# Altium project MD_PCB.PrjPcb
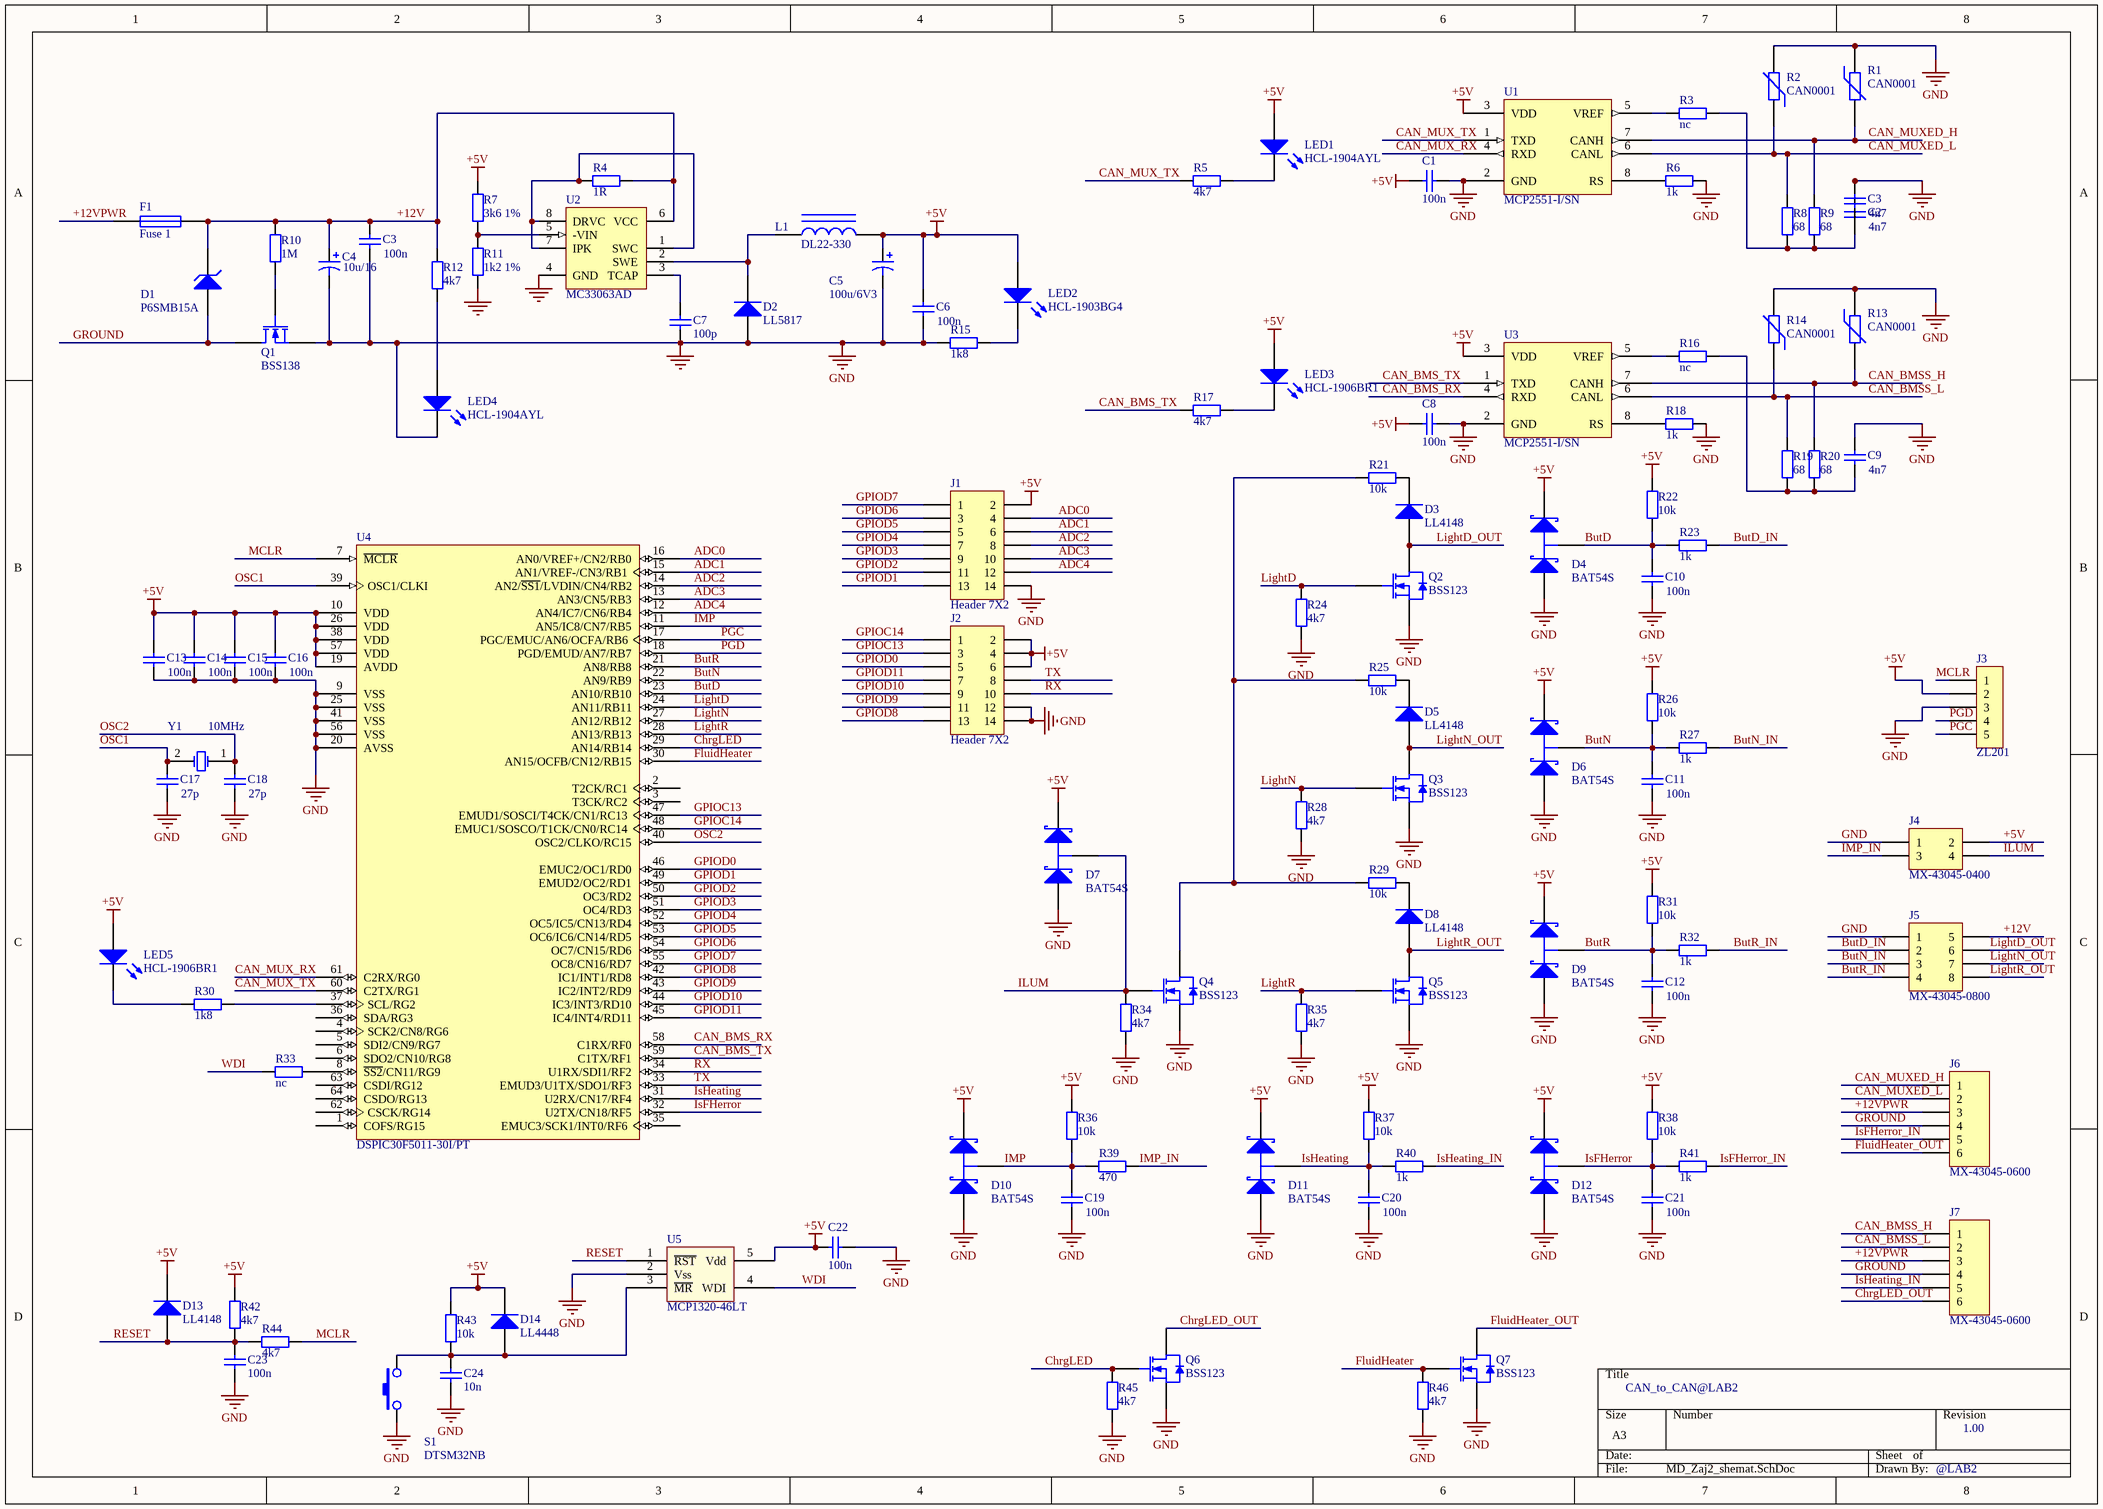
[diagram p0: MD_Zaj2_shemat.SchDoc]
1 sheet, 113 parts. Net scope: global (net labels, ports and power ports of the same name join across sheets).
Board file: PCB1.PcbDoc

## Sheet MD_Zaj2_shemat.SchDoc: CAN-to-CAN
size A3; Revision: PW-Test-Lab2; PageSetup: Record=PageOptions¦CenterHorizontal=True¦CenterVertical=True¦PrintScale=0.71¦XCorrection=1.00¦YCorrection=1.00¦PrintKind=1¦BorderSize=5000000¦LeftOffset=0¦BottomOffset=0¦Orientation=2¦PaperLength=2970¦PaperWidth=2100¦Scale=100¦PaperSource=7¦PrintQuality=1200¦MediaType=1¦DitherType=10¦PaperKind=A4¦PrintScaleMode=1

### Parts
(Parts that share a designator on the sheet are numbered #1, #2 ... from top to bottom, then left to right.)
C1  100n  [0603]
C2  4n7  [0603]
C3#1  4n7  [0603]
C3#2  100n  [0603]
C4  10u/16  [0603]
C5  100u/6V3  [0603]
C6  100n  [0603]
C7  100p  [0603]
C8  100n  [0603]
C9  4n7  [0603]
C10  100n  [0603]
C11  100n  [0603]
C12  100n  [0603]
C13  100n  [0603]
C14  100n  [0603]
C15  100n  [0603]
C16  100n  [0603]
C17  27p  [0603]
C18  27p  [0603]
C19  100n  [0603]
C20  100n  [0603]
C21  100n  [0603]
C22  100n  [0603]
C23  100n  [0603]
C24  10n  [0603]
D1  P6SMB15A  [SMB]
D2  LL5817  [0603]
D3  LL4148  [0603]
D4  BAT54S  [SOT-23_L]
D5  LL4148  [0603]
D6  BAT54S  [SOT-23_L]
D7  BAT54S  [SOT-23_L]
D8  LL4148  [0603]
D9  BAT54S  [SOT-23_L]
D10  BAT54S  [SOT-23_L]
D11  BAT54S  [SOT-23_L]
D12  BAT54S  [SOT-23_L]
D13  LL4148  [0603]
D14  LL4448  [0603]
F1  Fuse 1  [1812]
J1  Header 7X2  [HDR2X7]
J2  Header 7X2  [HDR2X7]
J3  ZL201  [HDR1X5]
J4  MX-43045-0400  [SOT-343_L]
J5  MX-43045-0800  [SO8_L]
J6  MX-43045-0600  [MHDR1X6]
J7  MX-43045-0600  [MHDR1x6]
L1  DL22-330  [AXIAL-0.9]
LED1  HCL-1904AYL  [0603]
LED2  HCL-1903BG4  [0603]
LED3  HCL-1906BR1  [0603]
LED4  HCL-1904AYL  [0603]
LED5  HCL-1906BR1  [0603]
Q1  BSS138  [SOT23_L]
Q2  BSS123  [SOT-23_L]
Q3  BSS123  [SOT-23_L]
Q4  BSS123  [SOT-23_L]
Q5  BSS123  [SOT-23_L]
Q6  BSS123  [SOT-23_L]
Q7  BSS123  [SOT-23_L]
R1  CAN0001  [0603]
R2  CAN0001  [0603]
R3  nc  [0603]
R4  1R  [0603]
R5  4k7  [0603]
R6  1k  [0603]
R7  3k6 1%  [0603]
R8  68  [0603]
R9  68  [0603]
R10  1M  [0603]
R11  1k2 1%  [0603]
R12  4k7  [0603]
R13  CAN0001  [0603]
R14  CAN0001  [0603]
R15  1k8  [0603]
R16  nc  [0603]
R17  4k7  [0603]
R18  1k  [0603]
R19  68  [0603]
R20  68  [0603]
R21  10k  [0603]
R22  10k  [0603]
R23  1k  [0603]
R24  4k7  [0603]
R25  10k  [0603]
R26  10k  [0603]
R27  1k  [0603]
R28  4k7  [0603]
R29  10k  [0603]
R30  1k8  [0603]
R31  10k  [0603]
R32  1k  [0603]
R33  nc  [0603]
R34  4k7  [0603]
R35  4k7  [0603]
R36  10k  [0603]
R37  10k  [0603]
R38  10k  [0603]
R39  470  [0603]
R40  1k  [0603]
R41  1k  [0603]
R42  4k7  [0603]
R43  10k  [0603]
R44  4k7  [0603]
R45  4k7  [0603]
R46  4k7  [0603]
S1  DTSM32NB  [0603]
U1  MCP2551-I/SN  [so8_L]
U2  MC33063AD  [SO8_N]
U3  MCP2551-I/SN  [SO8_L]
U4  DSPIC30F5011-30I/PT  [TQFP-PT64_L]
U5  MCP1320-46LT  [SOT-143_L]
Y1  10MHz  [0603]

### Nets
+5V: C1.1 C5.1 C6.1 C8.1 C13.1 C14.1 C15.1 C16.1 C22.1 D4.2(K) D6.2(K) D7.2(K) D9.2(K) D10.2(K) D11.2(K) D12.2(K) D13.2(K) D14.2(K) J1.2 J2.2 J2.4 J2.6 J3.2 J4.2 L1.2 LED1.1(A) LED2.1(A) LED3.1(A) LED5.1(A) R7.1 R22.1 R26.1 R31.1 R36.1 R37.1 R38.1 R42.1 R43.2 U1.3(VDD) U3.3(VDD) U4.10(VDD) U4.19(AVDD) U4.26(VDD) U4.38(VDD) U4.57(VDD) U5.5(Vdd)
GND: C1.2 C2.1 C3#1.1 C3#2.2 C4.2 C5.2 C6.2 C7.1 C8.2 C9.1 C10.2 C11.2 C12.2 C13.2 C14.2 C15.2 C16.2 C17.2 C18.2 C19.2 C20.2 C21.2 C22.2 C23.1 C24.1 D2.1(A) D4.1(A) D6.1(A) D7.1(A) D9.1(A) D10.1(A) D11.1(A) D12.1(A) J1.14 J2.12 J2.14 J3.3 J4.1 J5.1 LED4.2(K) Q1.2(S) Q2.2(S) Q3.2(S) Q4.2(S) Q5.2(S) Q6.2(S) Q7.2(S) R1.1 R2.2 R6.2 R11.1 R13.1 R14.2 R15.2 R18.2 R24.2 R28.2 R34.2 R35.2 R45.2 R46.2 S1.1 U1.2(GND) U2.4(GND) U3.2(GND) U4.9(VSS) U4.20(AVSS) U4.25(VSS) U4.41(VSS) U4.56(VSS) U5.2(Vss)
+12V: C3#2.1 C4.1 D1.2(K) F1.2 J5.5 R4.2 R10.1 R12.1 U2.6(VCC)
+12VPWR: F1.1 J6.3 J7.3
ADC0: J1.4 U4.16(AN0/VREF+/CN2/RB0)
ADC1: J1.6 U4.15(AN1/VREF-/CN3/RB1)
ADC2: J1.8 U4.14(AN2/~{SS1}/LVDIN/CN4/RB2)
ADC3: J1.10 U4.13(AN3/CN5/RB3)
ADC4: J1.12 U4.12(AN4/IC7/CN6/RB4)
ButD: C10.1 D4.3(C) R22.2 R23.2 U4.23(AN10/RB10)
ButD_IN: J5.2 R23.1
ButN: C11.1 D6.3(C) R26.2 R27.2 U4.22(AN9/RB9)
ButN_IN: J5.3 R27.1
ButR: C12.1 D9.3(C) R31.2 R32.2 U4.21(AN8/RB8)
ButR_IN: J5.4 R32.1
CAN_BMS_RX: U3.4(RXD) U4.58(C1RX/RF0)
CAN_BMS_TX: R17.2 U3.1(TXD) U4.59(C1TX/RF1)
CAN_BMSS_H: J7.1 R13.2 R20.1 U3.7(CANH)
CAN_BMSS_L: J7.2 R14.1 R19.1 U3.6(CANL)
CAN_MUX_RX: U1.4(RXD) U4.61(C2RX/RG0)
CAN_MUX_TX: R5.2 U1.1(TXD) U4.60(C2TX/RG1)
CAN_MUXED_H: J6.1 R1.2 R9.1 U1.7(CANH)
CAN_MUXED_L: J6.2 R2.1 R8.1 U1.6(CANL)
ChrgLED: Q6.3(G) R45.1 U4.29(AN14/RB14)
ChrgLED_OUT: J7.6 Q6.1(D)
FluidHeater: Q7.3(G) R46.1 U4.30(AN15/OCFB/CN12/RB15)
FluidHeater_OUT: J6.6 Q7.1(D)
GPIOC13: J2.3 U4.47(EMUD1/SOSCI/T4CK/CN1/RC13)
GPIOC14: J2.1 U4.48(EMUC1/SOSCO/T1CK/CN0/RC14)
GPIOD0: J2.5 U4.46(EMUC2/OC1/RD0)
GPIOD1: J1.13 U4.49(EMUD2/OC2/RD1)
GPIOD2: J1.11 U4.50(OC3/RD2)
GPIOD3: J1.9 U4.51(OC4/RD3)
GPIOD4: J1.7 U4.52(OC5/IC5/CN13/RD4)
GPIOD5: J1.5 U4.53(OC6/IC6/CN14/RD5)
GPIOD6: J1.3 U4.54(OC7/CN15/RD6)
GPIOD7: J1.1 U4.55(OC8/CN16/RD7)
GPIOD8: J2.13 U4.42(IC1/INT1/RD8)
GPIOD9: J2.11 U4.43(IC2/INT2/RD9)
GPIOD10: J2.9 U4.44(IC3/INT3/RD10)
GPIOD11: J2.7 U4.45(IC4/INT4/RD11)
GROUND: D1.1(A) J6.4 J7.4 Q1.1(D)
ILUM: D7.3(C) J4.4 Q4.3(G) R34.1
IMP: C19.1 D10.3(C) R36.2 R39.2 U4.11(AN5/IC8/CN7/RB5)
IMP_IN: J4.3 R39.1
IsFHerror: C21.1 D12.3(C) R38.2 R41.2 U4.32(U2TX/CN18/RF5)
IsFHerror_IN: J6.5 R41.1
IsHeating: C20.1 D11.3(C) R37.2 R40.2 U4.31(U2RX/CN17/RF4)
IsHeating_IN: J7.5 R40.1
LightD: Q2.3(G) R24.1 U4.24(AN11/RB11)
LightD_OUT: D3.1(A) J5.6 Q2.1(D)
LightN: Q3.3(G) R28.1 U4.27(AN12/RB12)
LightN_OUT: D5.1(A) J5.7 Q3.1(D)
LightR: Q5.3(G) R35.1 U4.28(AN13/RB13)
LightR_OUT: D8.1(A) J5.8 Q5.1(D)
MCLR: J3.1 R44.1 U4.7(~{MCLR})
OSC1: C17.1 U4.39(OSC1/CLKI) Y1.2(OSC2)
OSC2: C18.1 U4.40(OSC2/CLKO/RC15) Y1.1(OSC1)
PGC: J3.5 U4.17(PGC/EMUC/AN6/OCFA/RB6)
PGD: J3.4 U4.18(PGD/EMUD/AN7/RB7)
RESET: C23.2 D13.1(A) R42.2 R44.2 U5.1(~{RST})
RX: J2.10 U4.34(U1RX/SDI1/RF2)
TX: J2.8 U4.33(EMUD3/U1TX/SDO1/RF3)
WDI: R33.2 U5.4(WDI)
NetC2_2: C2.2 R3.2 R8.2 R9.2
NetC7_2: C7.2 U2.3(TCAP)
NetC9_2: C9.2 R16.2 R19.2 R20.2
NetC24_2: C24.2 D14.1(A) R43.1 S1.2 U5.3(~{MR})
NetD2_2: D2.2(K) L1.1 U2.2(SWE)
NetD3_2: D3.2(K) R21.2
NetD5_2: D5.2(K) R25.2
NetD8_2: D8.2(K) R29.2
NetLED1_2: LED1.2(K) R5.1
NetLED2_2: LED2.2(K) R15.1
NetLED3_2: LED3.2(K) R17.1
NetLED4_1: LED4.1(A) R12.2
NetLED5_2: LED5.2(K) R30.2
NetQ1_3: Q1.3(G) R10.2
NetQ4_1: Q4.1(D) R21.1 R25.1 R29.1
NetR3_1: R3.1 U1.5(VREF)
NetR4_1: R4.1 U2.1(SWC) U2.7(IPK) U2.8(DRVC)
NetR6_1: R6.1 U1.8(RS)
NetR7_2: R7.2 R11.2 U2.5(-VIN)
NetR16_1: R16.1 U3.5(VREF)
NetR18_1: R18.1 U3.8(RS)
NetR30_1: R30.1 U4.37(SCL/RG2)
NetR33_1: R33.1 U4.8(~{SS2}/CN11/RG9)

Not connected (* = marked no-connect by the designer): C3#1 2; U4 1(COFS/RG15) 2(T2CK/RC1) 3(T3CK/RC2) 4(SCK2/CN8/RG6) 5(SDI2/CN9/RG7) 6(SDO2/CN10/RG8) 35(EMUC3/SCK1/INT0/RF6) 36(SDA/RG3) 62(CSCK/RG14) 63(CSDI/RG12) 64(CSDO/RG13)

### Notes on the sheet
- CAN_to_CAN@LAB2
- 1.00
- @LAB2

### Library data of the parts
C1 C3#2 C6 C8 C10-C16 C19-C23 = Cap: Capacitor
C2 C3#1 C9 C17 C18 = Cap: Capacitor; Value: 100n
C4 C5 = Cap Pol1: Polarized Capacitor (Radial); Value: 470u/16
C7 C24 = Cap: Capacitor; Value: 100pF
D1 = D Zener: Zener Diode
D2 D3 D5 D8 D13 = 1N4148: High Conductance Fast Diode
D4 D6 D7 D9-D12 = BAT54S: Schottky Barrier Double Diode
D14 = Diode: Default Diode
F1 = Fuse 1: Fuse
J1 J2 = Header 7X2: Header, 7-Pin, Dual row
J3 = CON5: Connector
J4 = Header 2X2: Header, 2-Pin, Dual row
J5 = Header 4X2A: Header, 4-Pin, Dual row
J6 J7 = Header 6: Header, 6-Pin
L1 = Inductor Iron: Magnetic-Core Inductor; Value: 100uH
LED1-LED5 = LED3: Typical BLUE SiC LED; Revision 1: Jul-2002: Re-released for DXP Platform.; Revision 2: 17-Dec-2003: PCB Footprint replaced.
Q1 = BSS138: N-Channel Enhancement Mode Vertical DMOS FET
Q2-Q7 = BSS123: N-channel Enhancement Mode Vertical D-MOSFET
R1 R2 R13 R14 = Res Varistor: Varistor (Voltage-Sensitive Resistor)
R3-R5 R7-R12 R15-R17 R19-R22 R24-R26 R28-R31 R33-R39 R42-R46 = Res2: Resistor; Value: 1K
R6 R18 R23 R27 R32 R40 R41 = Res2: Resistor
S1 = PUSHB: Switch PushButton
U1 U3 = MCP2551-I/SN: High Speed CAN Transceiver, 8-Pin Plastic SOIC, Industrial Grade
U2 = MC33063AD: DC-to-DC Converter Control Circuit
U4 = CMP-0044-00148-1: High-Performance 16-bit Digital Signal Controller, 66 KB Flash, 4 KB SRAM, 1 KB EEPROM, 64-Pin TQFP, Industrial Temperature
U5 = MCP1320
Y1 = XTAL: Crystal Oscillator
